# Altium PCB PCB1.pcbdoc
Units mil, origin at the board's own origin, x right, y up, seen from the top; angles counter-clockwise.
Board outline 8360 x 1500 mil, 2 copper layers (Top Layer, Bottom Layer); 7 components, 9 nets, 33 pads, 0 vias.
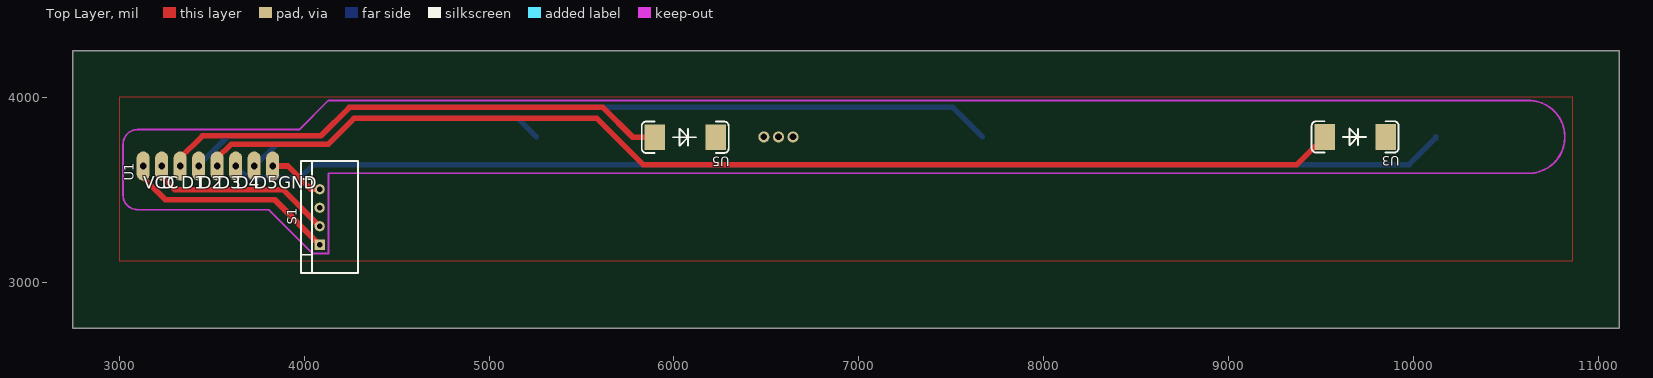
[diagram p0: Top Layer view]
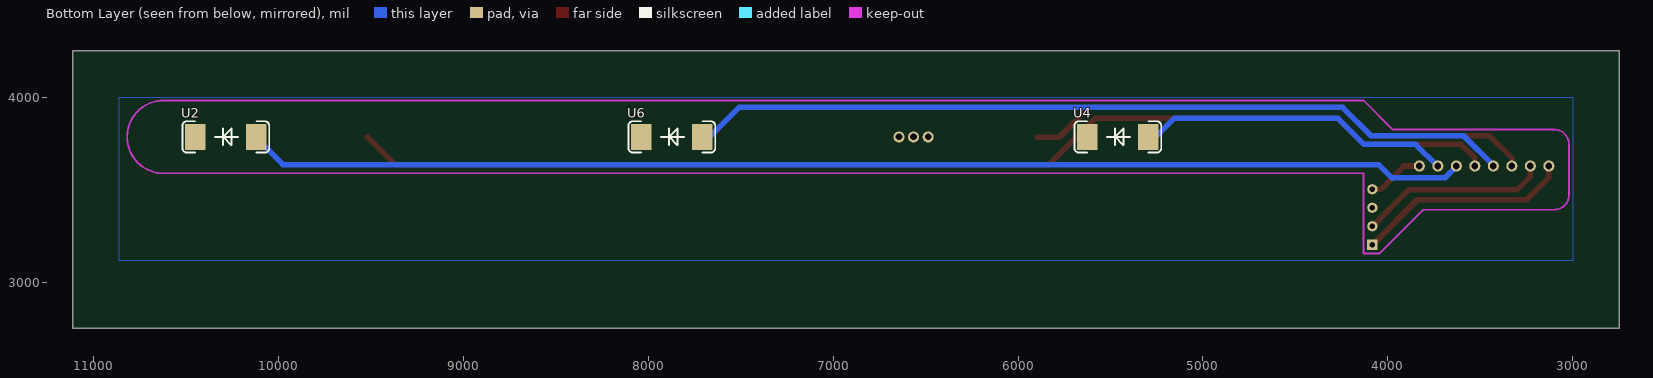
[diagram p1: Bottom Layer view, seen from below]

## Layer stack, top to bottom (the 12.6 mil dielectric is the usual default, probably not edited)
Top Layer: signal copper (thickness not stored)
Dielectric: dielectric 12.6, FR-4, Dk 4.8
Bottom Layer: signal copper (thickness not stored)

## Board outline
11110,2750 2750,2750 2750,4250 11110,4250

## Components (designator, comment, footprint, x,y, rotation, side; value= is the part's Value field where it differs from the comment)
S1 "AM2302" SENSOR-TH_AM2302 4084.33,3351.93 r90 top
U1 "PIN-8" PIN-8 3130,3627.52 r90 top
U2 "Adafruit_LED_4x9" LED_4x9 10283.15,3785 r180 bottom
U3 "Adafruit_LED_4x9" LED_4x9 9682.76,3785 r180 top
U4 "Adafruit_LED_4x9" LED_4x9 5460.31,3785 r180 bottom
U5 "Adafruit_LED_4x9" LED_4x9 6060.71,3783.04 r180 top
U6 "Adafruit_LED_4x9" LED_4x9 7871.73,3785 r180 bottom

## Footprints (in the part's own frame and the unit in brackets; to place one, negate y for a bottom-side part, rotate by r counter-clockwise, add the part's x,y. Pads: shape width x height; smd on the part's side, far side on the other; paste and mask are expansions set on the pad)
LED_4x9 [mil]
  rect 110x140 smd mask+2: 1(-165,0) 2(165,0)
  silkscreen extent -235,-85 235,85
PIN-8 [mm]
  oval 4x1.8 smd mask+0.051: 1(0,0) 2(0,-2.54) 3(0,-5.08) 4(0,-7.62) 5(0,-10.16) 6(0,-12.7) 7(0,-15.24) 8(0,-17.78)
SENSOR-TH_AM2302 [mm]
  rect 1.4x1.4 hole 0.8 mask+0.051: 1(-3.81,0)
  round 1.4 hole 0.8 mask+0.051: 2(-1.27,0) 3(1.27,0) 4(3.81,0)
  silkscreen extent -7.71,-5.26 7.7,2.54

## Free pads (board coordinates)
  round 60 hole 36 mask+2: 9(3130,3627.52) 10(3230,3627.52) 11(3330,3627.52) 12(3430,3627.52) 13(3530,3627.52) 14(3630,3627.52) 15(3730,3627.52) 16(3830,3627.52) 17(6485.91,3785) 18(6564.65,3785) 19(6643.39,3785)

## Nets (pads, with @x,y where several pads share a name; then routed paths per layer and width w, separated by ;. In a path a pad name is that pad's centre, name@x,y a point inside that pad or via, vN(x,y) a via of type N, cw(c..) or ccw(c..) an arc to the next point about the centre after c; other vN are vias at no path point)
$1N1514: pad.9 S1.1 U1.1 | length 1167.2
  Top Layer w30: pad.9 3130,3565 3250,3445 3841.26,3445 S1.1
$1N1517: pad.10 S1.2 U1.2 | length 1022.9
  Top Layer w30: pad.10 3230,3570 3300,3500 3886.26,3500 S1.2
$1N1520: pad.11 U1.3 U5.2 | length 2746.7
  Top Layer w30: U1.3@3330,3670 3450,3790 4090,3790 4245,3945 5615,3945 5776.96,3783.04 U5.2
$1N1527: pad.12 U1.4 U6.2 | length 4436.6
  Bottom Layer w30: pad.12 3430,3630 3590,3790 4090,3790 4245,3945 7507.36,3945 U6.2@7667.36,3785
$1N1535: pad.13 U1.5 U3.2 | length 6242.5
  Top Layer w30: U1.5@3530,3670 3605,3745 4130,3745 4270,3885 5583,3885 5833,3635 9367.76,3635 U3.2
$1N1558: pad.14 U1.6 U2.2 | length 6610.7
  Bottom Layer w30: pad.14 3630,3625 3690,3565 3980,3565 4050,3635 9975,3635 10118.15,3778.15 U2.2
$1N1565: pad.15 U1.7 U4.2 | length 1674
  Bottom Layer w30: pad.15 3732.52,3627.52 3850,3745 4130,3745 4270,3885 5155.94,3885 U4.2@5255.94,3785
$1N1569: pad.16 pad.17 pad.18 pad.19 S1.4 U1.8 U2.1 U3.1 U4.1 U5.1 U6.1 | length 306.4
  Top Layer w30: pad.16 3912.48,3627.52 4038.07,3501.93 S1.4
"": S1.3

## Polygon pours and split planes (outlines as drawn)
$1N1569 on Top Layer (solid, remove dead copper, pour order 0): 3000,3115 10860,3115 10860,4000 3000,4000
$1N1569 on Bottom Layer (solid, remove dead copper, pour order 1): 3000,3115 10860,3115 10860,4000 3000,4000

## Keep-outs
Board Outline Layer:
  lines w10 net "": 3100.08,3824.37 3974.09,3824.37 4131.57,3981.85 10619.76,3981.85 cw(c10619.76,3785) 10619.76,3588.15 4131.57,3588.15 4131.57,3155.08 4044.96,3155.08 3808.74,3391.3 3100.08,3391.3 cw(c3100.08,3470.04) 3021.34,3470.04 3021.34,3745.63 cw(c3100.08,3745.63) 3100.58,3824.37

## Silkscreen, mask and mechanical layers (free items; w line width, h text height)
Top Silkscreen Layer:
  text "VCC" at 3129.57,3505.05 h67.97
  text "D" at 3229.57,3505.05 h67.97
  text "D1" at 3334.57,3505.05 h67.97
  text "D2" at 3429.57,3505.05 h67.97
  text "D3" at 3529.57,3505.05 h67.97
  text "D4" at 3629.57,3505.05 h67.97
  text "D5" at 3729.57,3505.05 h67.97
  text "GND" at 3859.57,3505.05 h67.97
Mech6:
  lines w10 net "": 4130,3000 4130,3875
